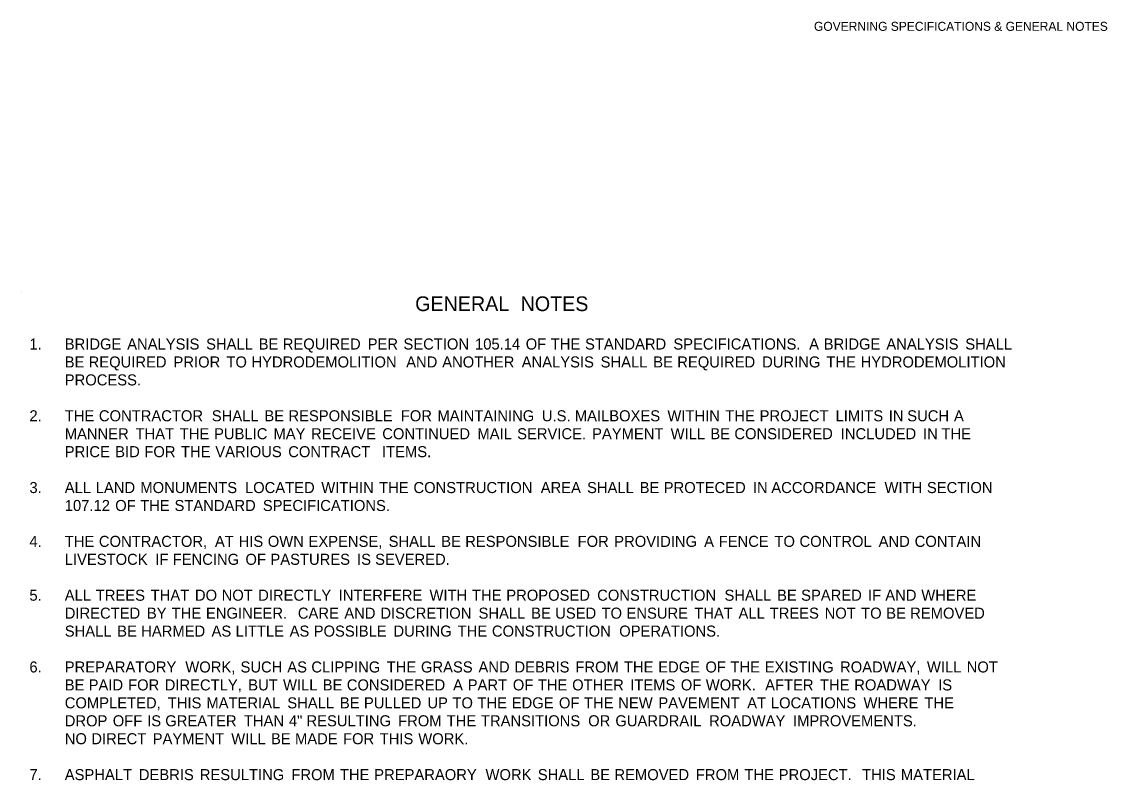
# Model space of a CAD drawing. Extents: x 1930579 to 1935504, y 596431 to 597414.
# Drawn here: x 1934796 to 1935504, y 596919 to 597414 of the extents above; entities that cross this region are included whole.
import ezdxf

# ---------------------------------------------------------------- set-up
doc = ezdxf.new("R2010")
doc.units = 0
for name, color, linetype in [('Default', 7, 'Continuous'), ('R_Border', 7, 'Continuous'), ('R_Border Prem', 7, 'Continuous')]:
    doc.layers.add(name, color=color, linetype=linetype)

msp = doc.modelspace()

# ---------------------------------------------------------------- linework, layer by layer
at = {"layer": 'R_Border'}
msp.add_line((1934796.12, 597237.62), (1934796.12, 597237.62), dxfattribs=at)

# ---------------------------------------------------------------- texts
at = {"layer": 'Default'}
for s, height, p in [('GENERAL', 9.6, (1935052.74, 597224.92)), (' NOTES', 9.6, (1935117.93, 597224.92)), ('1.', 7.2, (1934801.15, 597199.86)), ('BRIDGE', 7.2, (1934824.2, 597199.86)), (' ANALYSIS', 7.2, (1934862.24, 597199.86)), (' SHALL', 7.2, (1934913.72, 597199.86)), (' BE', 7.2, (1934948.03, 597199.86)), (' REQUIRED', 7.2, (1934963.7, 597199.86)), (' PER', 7.2, (1935019.07, 597199.86)), (' SECTION', 7.2, (1935042.41, 597199.86)), (' 105.14', 7.2, (1935089.1, 597199.86)), (' OF', 7.2, (1935122.16, 597199.86)), (' THE', 7.2, (1935138.46, 597199.86)), (' STANDARD', 7.2, (1935160.84, 597199.86)), (' SPECIFICATIONS.', 7.2, (1935218.44, 597199.86)), (' A', 7.2, (1935307, 597199.86)), (' BRIDGE', 7.2, (1935316.53, 597199.86)), (' ANALYSIS', 7.2, (1935357.36, 597199.86)), (' SHALL', 7.2, (1935408.83, 597199.86)), ('BE', 7.2, (1934824.2, 597188.16)), (' REQUIRED', 7.2, (1934837.09, 597188.16)), (' PRIOR', 7.2, (1934892.45, 597188.16)), (' TO', 7.2, (1934926.97, 597188.16)), (' HYDRODEMOLITION', 7.2, (1934943.28, 597188.16)), (' AND', 7.2, (1935044.19, 597188.16)), (' ANOTHER', 7.2, (1935067.69, 597188.16)), (' ANALYSIS', 7.2, (1935119.54, 597188.16)), (' SHALL', 7.2, (1935171.01, 597188.16)), (' BE', 7.2, (1935205.32, 597188.16)), (' REQUIRED', 7.2, (1935221, 597188.16)), (' DURING', 7.2, (1935276.36, 597188.16)), (' THE', 7.2, (1935318.21, 597188.16)), (' HYDRODEMOLITION', 7.2, (1935340.58, 597188.16)), ('PROCESS.', 7.2, (1934824.2, 597176.46)), ('2.', 7.2, (1934801.15, 597153.06)), ('THE', 7.2, (1934824.2, 597153.06)), (' CONTRACTOR', 7.2, (1934843.79, 597153.06)), (' SHALL', 7.2, (1934917.43, 597153.06)), (' BE', 7.2, (1934951.74, 597153.06)), (' RESPONSIBLE', 7.2, (1934967.42, 597153.06)), (' FOR', 7.2, (1935040.69, 597153.06)), (' MAINTAINING', 7.2, (1935064.58, 597153.06)), (' U.S.', 7.2, (1935132.7, 597153.06)), (' MAILBOXES', 7.2, (1935154.17, 597153.06)), (' WITHIN', 7.2, (1935214.59, 597153.06)), (' THE', 7.2, (1935252.32, 597153.06)), (' PROJECT', 7.2, (1935274.7, 597153.06)), (' LIMITS', 7.2, (1935324.25, 597153.06)), (' IN', 7.2, (1935358.93, 597153.06)), (' SUCH', 7.2, (1935370.96, 597153.06)), (' A', 7.2, (1935401.45, 597153.06)), ('MANNER', 7.2, (1934824.2, 597141.36)), (' THAT', 7.2, (1934867.67, 597141.36)), (' THE', 7.2, (1934896.53, 597141.36)), (' PUBLIC', 7.2, (1934918.91, 597141.36)), (' MAY', 7.2, (1934957.64, 597141.36)), (' RECEIVE', 7.2, (1934982.16, 597141.36)), (' CONTINUED', 7.2, (1935028.59, 597141.36)), (' MAIL', 7.2, (1935090.65, 597141.36)), (' SERVICE.', 7.2, (1935116.56, 597141.36)), (' PAYMENT', 7.2, (1935165.44, 597141.36)), (' WILL', 7.2, (1935216.67, 597141.36)), (' BE', 7.2, (1935242.58, 597141.36)), (' CONSIDERED', 7.2, (1935258.26, 597141.36)), (' INCLUDED', 7.2, (1935327.6, 597141.36)), (' IN', 7.2, (1935381.28, 597141.36)), (' THE', 7.2, (1935393.31, 597141.36)), ('PRICE', 7.2, (1934824.2, 597129.66)), (' BID', 7.2, (1934854.41, 597129.66)), (' FOR', 7.2, (1934873.44, 597129.66)), (' THE', 7.2, (1934897.33, 597129.66)), (' VARIOUS', 7.2, (1934919.71, 597129.66)), (' CONTRACT', 7.2, (1934967.27, 597129.66)), ('  ITEMS.', 7.2, (1935025.75, 597129.66)), ('3.', 7.2, (1934801.15, 597106.26)), ('ALL', 7.2, (1934824.2, 597106.26)), (' LAND', 7.2, (1934841.74, 597106.26)), (' MONUMENTS', 7.2, (1934870.83, 597106.26)), (' LOCATED', 7.2, (1934939.05, 597106.26)), (' WITHIN', 7.2, (1934988.83, 597106.26)), (' THE', 7.2, (1935026.56, 597106.26)), (' CONSTRUCTION', 7.2, (1935048.94, 597106.26)), (' AREA', 7.2, (1935131.95, 597106.26)), (' SHALL', 7.2, (1935162.16, 597106.26)), (' BE', 7.2, (1935196.47, 597106.26)), (' PROTECED', 7.2, (1935212.15, 597106.26)), (' IN', 7.2, (1935270.31, 597106.26)), (' ACCORDANCE', 7.2, (1935282.34, 597106.26)), (' WITH', 7.2, (1935356.15, 597106.26)), (' SECTION', 7.2, (1935383.83, 597106.26)), ('107.12', 7.2, (1934824.2, 597094.56)), (' OF', 7.2, (1934854.43, 597094.56)), (' THE', 7.2, (1934870.73, 597094.56)), (' STANDARD', 7.2, (1934893.11, 597094.56)), (' SPECIFICATIONS.', 7.2, (1934950.71, 597094.56)), ('4.', 7.2, (1934801.15, 597071.16)), ('THE', 7.2, (1934824.2, 597071.16)), (' CONTRACTOR,', 7.2, (1934843.79, 597071.16)), (' AT', 7.2, (1934919.47, 597071.16)), (' HIS', 7.2, (1934934.92, 597071.16)), (' OWN', 7.2, (1934953.95, 597071.16)), (' EXPENSE,', 7.2, (1934980.51, 597071.16)), (' SHALL', 7.2, (1935032.74, 597071.16)), (' BE', 7.2, (1935067.05, 597071.16)), (' RESPONSIBLE', 7.2, (1935082.72, 597071.16)), (' FOR', 7.2, (1935155.99, 597071.16)), (' PROVIDING', 7.2, (1935179.89, 597071.16)), (' A', 7.2, (1935238.51, 597071.16)), (' FENCE', 7.2, (1935248.03, 597071.16)), (' TO', 7.2, (1935284.38, 597071.16)), (' CONTROL', 7.2, (1935300.7, 597071.16)), (' AND', 7.2, (1935352.32, 597071.16)), (' CONTAIN', 7.2, (1935375.82, 597071.16)), ('LIVESTOCK', 7.2, (1934824.2, 597059.46)), (' IF', 7.2, (1934880.65, 597059.46)), (' FENCING', 7.2, (1934891.92, 597059.46)), (' OF', 7.2, (1934939.36, 597059.46)), (' PASTURES', 7.2, (1934955.66, 597059.46)), (' IS', 7.2, (1935012.17, 597059.46)), (' SEVERED.', 7.2, (1935023.94, 597059.46)), ('5.', 7.2, (1934801.15, 597036.06)), ('ALL', 7.2, (1934824.2, 597036.06)), (' TREES', 7.2, (1934841.74, 597036.06)), (' THAT', 7.2, (1934877.56, 597036.06)), (' DO', 7.2, (1934906.42, 597036.06)), (' NOT', 7.2, (1934923.85, 597036.06)), (' DIRECTLY', 7.2, (1934947.68, 597036.06)), (' INTERFERE', 7.2, (1935000.15, 597036.06)), (' WITH', 7.2, (1935059.42, 597036.06)), (' THE', 7.2, (1935087.1, 597036.06)), (' PROPOSED', 7.2, (1935109.48, 597036.06)), (' CONSTRUCTION', 7.2, (1935168.77, 597036.06)), (' SHALL', 7.2, (1935251.78, 597036.06)), (' BE', 7.2, (1935286.09, 597036.06)), (' SPARED', 7.2, (1935301.77, 597036.06)), (' IF', 7.2, (1935345.4, 597036.06)), (' AND', 7.2, (1935356.67, 597036.06)), (' WHERE', 7.2, (1935380.17, 597036.06)), ('DIRECTED', 7.2, (1934824.2, 597024.36)), (' BY', 7.2, (1934875.09, 597024.36)), (' THE', 7.2, (1934891.23, 597024.36)), (' ENGINEER.', 7.2, (1934913.61, 597024.36)), ('  CARE', 7.2, (1934970.87, 597024.36)), (' AND', 7.2, (1935003.87, 597024.36)), (' DISCRETION', 7.2, (1935027.37, 597024.36)), (' SHALL', 7.2, (1935091.39, 597024.36)), (' BE', 7.2, (1935125.7, 597024.36)), (' USED', 7.2, (1935141.38, 597024.36)), (' TO', 7.2, (1935171.59, 597024.36)), (' ENSURE', 7.2, (1935187.9, 597024.36)), (' THAT', 7.2, (1935232.09, 597024.36)), (' ALL', 7.2, (1935260.95, 597024.36)), (' TREES', 7.2, (1935281.28, 597024.36)), (' NOT', 7.2, (1935317.1, 597024.36)), (' TO', 7.2, (1935340.92, 597024.36)), (' BE', 7.2, (1935357.24, 597024.36)), (' REMOVED', 7.2, (1935372.92, 597024.36)), ('SHALL', 7.2, (1934824.2, 597012.66)), (' BE', 7.2, (1934855.72, 597012.66)), (' HARMED', 7.2, (1934871.4, 597012.66)), (' AS', 7.2, (1934917.26, 597012.66)), (' LITTLE', 7.2, (1934932.95, 597012.66)), (' AS', 7.2, (1934968.18, 597012.66)), (' POSSIBLE', 7.2, (1934983.87, 597012.66)), (' DURING', 7.2, (1935035.9, 597012.66)), (' THE', 7.2, (1935077.74, 597012.66)), (' CONSTRUCTION', 7.2, (1935100.12, 597012.66)), (' OPERATIONS.', 7.2, (1935183.13, 597012.66)), ('6.', 7.2, (1934801.15, 596989.26)), ('PREPARATORY', 7.2, (1934824.2, 596989.26)), (' WORK,', 7.2, (1934900.17, 596989.26)), (' SUCH', 7.2, (1934936.16, 596989.26)), (' AS', 7.2, (1934966.65, 596989.26)), (' CLIPPING', 7.2, (1934982.34, 596989.26)), (' THE', 7.2, (1935031.46, 596989.26)), (' GRASS', 7.2, (1935053.84, 596989.26)), (' AND', 7.2, (1935091.33, 596989.26)), (' DEBRIS', 7.2, (1935114.83, 596989.26)), (' FROM', 7.2, (1935154.55, 596989.26)), (' THE', 7.2, (1935186.21, 596989.26)), (' EDGE', 7.2, (1935208.59, 596989.26)), (' OF', 7.2, (1935239.36, 596989.26)), (' THE', 7.2, (1935255.66, 596989.26)), (' EXISTING', 7.2, (1935278.04, 596989.26)), (' ROADWAY,', 7.2, (1935327.16, 596989.26)), (' WILL', 7.2, (1935383.84, 596989.26)), (' NOT', 7.2, (1935409.75, 596989.26)), ('BE', 7.2, (1934824.2, 596977.56)), (' PAID', 7.2, (1934837.09, 596977.56)), (' FOR', 7.2, (1934862.83, 596977.56)), (' DIRECTLY,', 7.2, (1934886.72, 596977.56)), (' BUT', 7.2, (1934941.17, 596977.56)), (' WILL', 7.2, (1934963.88, 596977.56)), (' BE', 7.2, (1934989.79, 596977.56)), (' CONSIDERED', 7.2, (1935005.47, 596977.56)), (' A', 7.2, (1935074.8, 596977.56)), (' PART', 7.2, (1935084.33, 596977.56)), (' OF', 7.2, (1935113.75, 596977.56)), (' THE', 7.2, (1935130.06, 596977.56)), (' OTHER', 7.2, (1935152.44, 596977.56)), (' ITEMS', 7.2, (1935190.31, 596977.56)), (' OF', 7.2, (1935223.32, 596977.56)), (' WORK.', 7.2, (1935239.62, 596977.56)), ('  AFTER', 7.2, (1935275.63, 596977.56)), (' THE', 7.2, (1935314.06, 596977.56)), (' ROADWAY', 7.2, (1935336.44, 596977.56)), (' IS', 7.2, (1935391.14, 596977.56)), ('COMPLETED,', 7.2, (1934824.2, 596965.86)), (' THIS', 7.2, (1934888.71, 596965.86)), (' MATERIAL', 7.2, (1934913.9, 596965.86)), (' SHALL', 7.2, (1934966.65, 596965.86)), (' BE', 7.2, (1935000.96, 596965.86)), (' PULLED', 7.2, (1935016.63, 596965.86)), (' UP', 7.2, (1935058.03, 596965.86)), (' TO', 7.2, (1935074.36, 596965.86)), (' THE', 7.2, (1935090.68, 596965.86)), (' EDGE', 7.2, (1935113.05, 596965.86)), (' OF', 7.2, (1935143.82, 596965.86)), (' THE', 7.2, (1935160.13, 596965.86)), (' NEW', 7.2, (1935182.51, 596965.86)), (' PAVEMENT', 7.2, (1935208.66, 596965.86)), (' AT', 7.2, (1935266.6, 596965.86)), (' LOCATIONS', 7.2, (1935282.05, 596965.86)), (' WHERE', 7.2, (1935342.45, 596965.86)), (' THE', 7.2, (1935382.15, 596965.86)), ('DROP', 7.2, (1934824.2, 596954.16)), (' OFF', 7.2, (1934852.83, 596954.16)), (' IS', 7.2, (1934875.28, 596954.16)), (' GREATER', 7.2, (1934887.06, 596954.16)), (' THAN', 7.2, (1934938.35, 596954.16)), (' 4"', 7.2, (1934967.71, 596954.16)), (' RESULTING', 7.2, (1934979.2, 596954.16)), (' FROM', 7.2, (1935038.94, 596954.16)), (' THE', 7.2, (1935070.59, 596954.16)), (' TRANSITIONS', 7.2, (1935092.97, 596954.16)), (' OR', 7.2, (1935162.87, 596954.16)), (' GUARDRAIL', 7.2, (1935180.62, 596954.16)), (' ROADWAY', 7.2, (1935241.75, 596954.16)), (' IMPROVEMENTS.', 7.2, (1935296.46, 596954.16)), ('NO', 7.2, (1934824.2, 596942.46)), (' DIRECT', 7.2, (1934838.85, 596942.46)), (' PAYMENT', 7.2, (1934878.88, 596942.46)), (' WILL', 7.2, (1934930.11, 596942.46)), (' BE', 7.2, (1934956.02, 596942.46)), (' MADE', 7.2, (1934971.7, 596942.46)), (' FOR', 7.2, (1935003.02, 596942.46)), (' THIS', 7.2, (1935026.92, 596942.46)), (' WORK.', 7.2, (1935052.1, 596942.46)), ('7.', 7.2, (1934801.15, 596919.06)), ('ASPHALT', 7.2, (1934824.2, 596919.06)), (' DEBRIS', 7.2, (1934869.85, 596919.06)), (' RESULTING', 7.2, (1934909.58, 596919.06)), (' FROM', 7.2, (1934969.32, 596919.06)), (' THE', 7.2, (1935000.97, 596919.06)), (' PREPARAORY', 7.2, (1935023.35, 596919.06)), (' WORK', 7.2, (1935095.96, 596919.06)), (' SHALL', 7.2, (1935130.03, 596919.06)), (' BE', 7.2, (1935164.34, 596919.06)), (' REMOVED', 7.2, (1935180.02, 596919.06)), (' FROM', 7.2, (1935233.14, 596919.06)), (' THE', 7.2, (1935264.8, 596919.06)), (' PROJECT.', 7.2, (1935287.18, 596919.06)), ('  THIS', 7.2, (1935338.85, 596919.06)), (' MATERIAL', 7.2, (1935366.82, 596919.06))]:
    msp.add_text(s, height=height, rotation=360, dxfattribs=at).set_placement(p)
at = {"layer": 'R_Border Prem'}
msp.add_text('GOVERNING SPECIFICATIONS & GENERAL NOTES', height=5.862, rotation=360, dxfattribs=at).set_placement((1935312.83, 597407.69))

doc.saveas('drawing.dxf')
